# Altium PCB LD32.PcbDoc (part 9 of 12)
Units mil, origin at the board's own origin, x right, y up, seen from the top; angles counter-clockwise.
Board outline 7007.87 x 4368.85 mil, 12 copper layers (Top Layer, Int1 (GND), Int2 (AVDD), Int3 (DVDD), Int4 (GND), Int5 (ST), Int6 (SB), Int8 (AGND), Int7 (AVCC), Int9 (VCCA), Int10 (GND), Bottom Layer), stack 60.136 mil thick; 1165 components, 667 nets, 3910 pads, 2570 vias.
Unrouted connection lines stored in the file: 14.
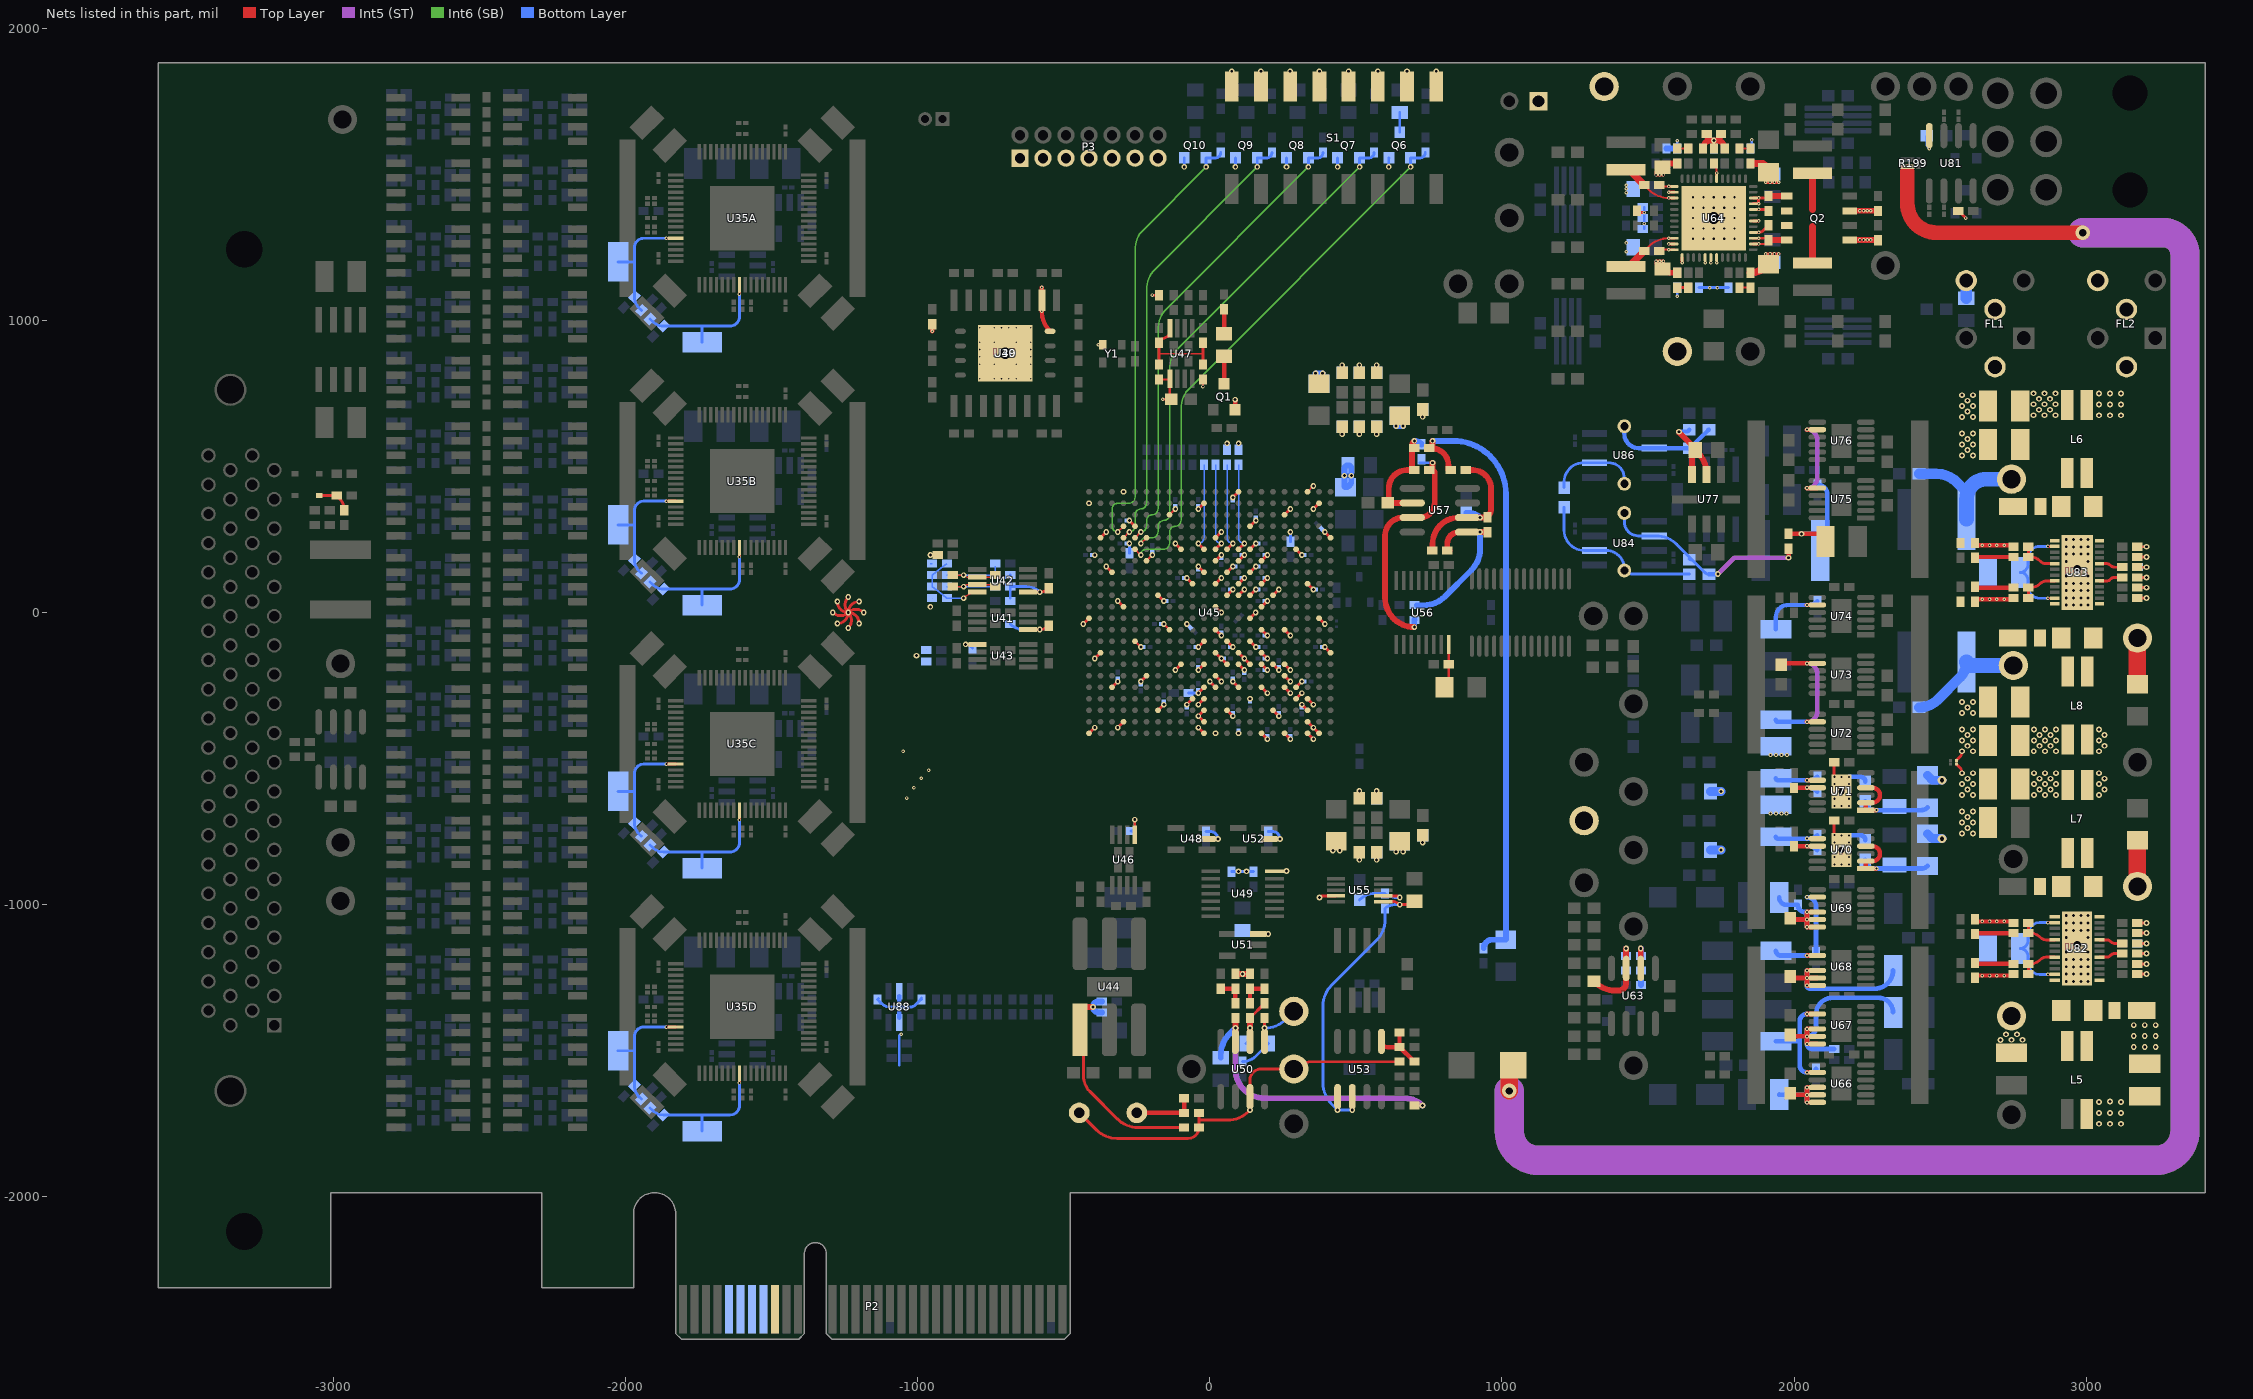
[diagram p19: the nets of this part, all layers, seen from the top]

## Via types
v1: diameter 12, hole 6, Top Layer to Bottom Layer, tented both sides, 1500 vias
v2: diameter 19, hole 10, Top Layer to Bottom Layer, tented both sides, 404 vias
v3: diameter 20, hole 10, Top Layer to Bottom Layer, tented both sides, 337 vias
v4: diameter 14, hole 7, Top Layer to Bottom Layer, tented both sides, 212 vias
v5: diameter 30, hole 15, Top Layer to Bottom Layer, tented both sides, 37 vias
v6: diameter 19.68, hole 7.87, Top Layer to Bottom Layer, 25 vias
v7: diameter 40, hole 20, Top Layer to Bottom Layer, tented both sides, 16 vias
v8: diameter 19.02, hole 10, Top Layer to Bottom Layer, tented both sides, 10 vias
v9: diameter 40, hole 20, Top Layer to Bottom Layer, 9 vias
v10: diameter 60, hole 40, Top Layer to Bottom Layer, 5 vias
v11: diameter 25, hole 13, Top Layer to Bottom Layer, 4 vias
v12: diameter 50, hole 25, Top Layer to Bottom Layer, tented both sides, 4 vias
v13: diameter 35, hole 20, Top Layer to Bottom Layer, 2 vias
v14: diameter 50, hole 25, Top Layer to Bottom Layer, 2 vias
v15: diameter 63, hole 45, Top Layer to Bottom Layer, 1 vias
v16: diameter 14.02, hole 7.01, Top Layer to Bottom Layer, tented both sides, 1 vias
v17: diameter 60, hole 40, Top Layer to Bottom Layer, tented both sides, 1 vias

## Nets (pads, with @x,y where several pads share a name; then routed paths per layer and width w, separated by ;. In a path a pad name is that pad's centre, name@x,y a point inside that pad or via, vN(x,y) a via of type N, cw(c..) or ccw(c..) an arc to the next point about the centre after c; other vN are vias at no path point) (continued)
GND: C62.1 C63.1 C65.1 C69.1 C70.1 C71.2 C72.1 C73.1 C74.1 C75.1 C76.1 C77.1 C78.1 C79.1 C80.1 C81.1 C82.1 C83.1 C84.1 C85.1 C91.1 C92.1 C100.1 C103.1 C104.1 C106.1 C107.1 C108.2 C109.1 C110.1 C111.1 C112.2 C113.1 C118.2 C119.1 C120.2 C121.1 C122.1 C123.2 C124.2 C125.1 C126.2 C127.1 C128.2 C129.2 C130.2 C131.1 C132.1 C137.1 C138.1 C139.2 C140.2 C141.1 C142.2 C143.2 C146.2 C147.2 C148.1 C149.1 C153.1 C154.1 C159.1 C160.1 C163.2 C164.2 C172.1 C173.2 C174.2 C175.2 C176.1 C182.1 C183.1 C185.1 C186.1 C189.1 C190.1 C191.1 C192.1 C194.2 C199.1 C200.1 C201.1 C202.1 C204.1 C205.1 C206.1 C207.1 C208.1 C209.1 C210.2 C211.1 C212.1 C213.2 C214.1 C216.2 C217.1 C218.2 C219.2 C220.2 C221.2 C222.2 C223.2 C224.2 C225.2 C226.2 C227.1 C228.1 C229.1 C230.1 C231.2 C232.2 C235.1 C236.2 C237.2 C238.1 C239.1 C240.1 C241.1 C242.2 C243.2 C244.1 C245.1 C246.2 C247.1 C249.1 C250.1 C251.1 C252.1 C253.1 C254.1 C255.1 C256.1 C257.1 C258.1 C259.1 C260.1 C261.1 C262.1 C263.1 C264.1 C265.1 C266.1 C268.2 C269.1 C270.1 C271.1 C273.1 C281.1 C283.1 C286.2 D7.2 FL1.4 FL1.5 FL1.6 FL2.4 FL2.5 FL2.6 FR8.1 L6.3 L7.3 L8.4 P3.1 P3.3 P3.5 P3.7 P3.9 P3.11 P3.13 P4.1 Q1.2 Q2.1 Q2.3 Q6.2 Q7.2 Q8.2 Q9.2 Q10.2 R69.2 R70.2 R98.2 R100.2 R148.2 R154.2 R156.2 R170.1 R171.1 R182.1 R183.1 R187.2 R188.2 R211.1 R212.1 R214.2 R217.2 R219.2 R220.2 R221.1 R237.1 R238.1 R246.1 R251.2 R256.2 R261.2 R265.1 R266.1 R267.1 R268.1 R269.2 R293.2 R294.2 R305.2 R306.2 R307.2 R309.1 R312.2 R314.1 R315.2 R316.1 S1.1 S1.2 S1.3 S1.4 S1.5 S1.6 S1.7 S1.8 TP13.1 TP16.1 TP23.1 TP32.1 U39.10 U40.4 U40.9 U41.5 U42.5 U43.5 U45.A2 U45.A3 U45.A5 U45.A7 U45.A9 U45.A11 U45.A12 U45.A22 U45.AA2 U45.AA12 U45.AA22 U45.AB9 U45.AB19 U45.B3 U45.B12 U45.B19 U45.C3 U45.C6 U45.C10 U45.C12 U45.C16 U45.D3 U45.D4 U45.D8 U45.D12 U45.D13 U45.E4 U45.E5 U45.E7 U45.E9 U45.E11 U45.E12 U45.E20 U45.F5 U45.F11 U45.F17 U45.G5 U45.G6 U45.G7 U45.G8 U45.G9 U45.G10 U45.G12 U45.G14 U45.H1 U45.H7 U45.H9 U45.H11 U45.H21 U45.J8 U45.J10 U45.J12 U45.J18 U45.K5 U45.K7 U45.K11 U45.K15 U45.L2 U45.L8 U45.L22 U45.M7 U45.M11 U45.M19 U45.N6 U45.N8 U45.N9 U45.N10 U45.N16 U45.P3 U45.P7 U45.P9 U45.P11 U45.P13 U45.R8 U45.R10 U45.R12 U45.R20 U45.T7 U45.T9 U45.T11 U45.T17 U45.U4 U45.U8 U45.U14 U45.V1 U45.V11 U45.V21 U45.W8 U45.W18 U45.Y5 U45.Y15 U46.5 U47.5 U48.2 U49.7 U51.3 U52.2 U55.9 U64.2 U64.11 U64.13 U64.17 U64.18 U64.19 U64.30 U64.49 U70.9 U70.13 U71.9 U71.13 U81.4 U82.25 U83.25 U88.2 U88.5 W1.1 W2.1 Y1.2 | length 8686.6
  Top Layer w7.99: U45.Y15@-137.8,334.65 v2(-118.11,354.33)
  Top Layer w8: U45.J18@-255.91,-98.43 v2(-236.22,-118.11) ; U45.T17@-216.54,177.17 v2(-196.85,196.85) ; v1(-196.85,1086.42) R100.2@-173.43,1086.42 ; R98.2@-173.43,797.74 -138.48,797.74 U47.5@-136.81,799.41 -136.81,729.58 v1(-160.93,729.58) ; v2(-157.48,-39.37) U45.K15@-137.8,-59.06 ; v1(-23.43,773.33) C69.1@-23.43,797.74
  Top Layer w10: v2(-956.69,196.85) R70.2@-931.1,196.85 ; v2(-835.96,-109.25) U43.5@-795.08,-109.25 ; U41.5@-622.24,-58.07 v2(-582.07,-58.07) ccw(c-582.07,-14.39) C63.1@-551.18,-45.28 ; U42.5@-622.24,69.88 v2(-582.07,69.88) ccw(c-582.07,113.57) C62.1@-551.18,82.68 ; v2(-433.07,-39.37) U45.L22@-413.39,-19.68 ; U45.A22@-413.39,-413.39 v2(-393.7,-393.7) ; v2(-393.72,-157.48) U45.H21@-374.02,-137.8 ; v1(-381.89,916.34) Y1.2@-367.13,916.34 ; U45.V21@-374.02,255.91 v2(-354.33,275.59) ; v2(-354.33,157.48) U45.R20@-334.65,137.8 ; U45.E20@-334.65,-255.91 U45.E20@-334.65,-255.91 v2(-314.96,-236.35) v2(-314.96,-236.35) ; v2(-314.96,-393.7) U45.B19@-295.28,-374.02 ; v2(-314.96,39.37) U45.M19@-295.28,19.69 ; v2(-275.59,314.96) U45.W18@-255.91,295.28 ; U46.5@-256.89,-760.04 v2(-256.89,-708.66) ; v2(-236.22,-236.22) U45.F17@-216.54,-216.54 ; U45.C16@-177.17,-334.65 v2(-157.48,-314.96) ; U45.N16@-177.17,59.06 v2(-157.48,39.37) ; v2(-118.11,-196.85) U45.G14@-98.43,-177.17 ; v2(-118.11,236.22) U45.U14@-98.43,216.54 ; v2(-78.74,-314.96) U45.D13@-59.05,-295.28 ; v2(-78.74,118.11) U45.P13@-59.05,98.43 ; v2(-39.37,-393.7) U45.A12@-19.68,-413.39 ; v2(-39.37,-314.96) U45.D12@-19.68,-295.28 ; v2(-39.37,-275.59) U45.E12@-19.68,-255.91 ; v2(-39.37,-196.85) U45.G12@-19.68,-177.17 ; v2(-39.37,-118.11) U45.J12@-19.68,-98.43 ; v2(-39.37,157.48) U45.R12@-19.68,137.8 ; v2(-39.37,354.33) U45.AA12@-19.68,374.02 ; U45.B12@-19.68,-374.02 v2(-39.37,-354.33) U45.C12@-19.68,-334.65 ; U48.2@-9.35,-775 v3(27.5,-775) ; v2@0,-236.22 U45.E11@19.69,-255.91 ; U45.F11@19.69,-216.54 v2(39.37,-236.22) ; U45.H11@19.69,-137.8 v2(39.37,-157.48) U45.G10@59.06,-177.17 ; U45.K11@19.69,-59.06 v2(39.37,-78.74) ; U45.M11@19.69,19.69 v2(39.37,0) ; U45.P11@19.69,98.43 v2(39.37,118.11) ; U45.T11@19.69,177.17 v2(39.37,196.85) ; U45.V11@19.69,255.91 v2(39.37,275.59) ; U45.C10@59.06,-334.65 v2(78.74,-354.33) ; U45.J10@59.06,-98.43 v2(78.74,-118.11) ; U45.N10@59.06,59.06 v2(78.74,78.74) ; U45.R10@59.06,137.8 v2(78.74,157.48) ; v2(78.74,-236.22) U45.E9@98.43,-255.91 ; v2(78.74,393.7) U45.AB9@98.43,413.39 ; U45.G9@98.43,-177.17 v2(118.11,-196.85) ; U45.H9@98.43,-137.8 v2(118.11,-157.48) U45.G8@137.8,-177.17 ; U45.N9@98.43,59.06 v2(118.11,78.74) ; U45.P9@98.43,98.43 v2(118.11,118.11) ; U45.T9@98.43,177.17 v2(118.11,196.85) ; U45.J8@137.8,-98.43 v2(157.48,-118.11) ; U45.L8@137.8,-19.68 v2(157.05,0) ; U45.N8@137.8,59.06 v2(157.48,78.74) ; U45.R8@137.8,137.8 v2(157.48,157.48) ; U45.U8@137.8,216.54 v2(157.48,236.22) ; U45.W8@137.8,295.28 v2(157.48,314.96) ; U45.A7@177.17,-413.39 v2(196.85,-433.07) ; U45.E7@177.17,-255.91 v2(196.85,-275.59) ; U45.G7@177.17,-177.17 v2(196.85,-196.85) ; U45.H7@177.17,-137.8 v2(196.85,-157.48) ; U45.K7@177.17,-59.06 v2(196.85,-78.74) ; U45.M7@177.17,19.69 v2(196.85,39.37) ; U45.P7@177.17,98.43 v2(196.85,118.11) ; U45.T7@177.17,177.17 v2(196.85,196.85) ; U45.C6@216.54,-334.65 v2(236.22,-354.33) ; U45.G6@216.54,-177.17 v2(236.22,-196.85) ; U45.N6@216.54,59.06 v2(236.22,78.74) ; U45.A5@255.91,-413.39 v2(275.59,-433.07) ; U45.E5@255.91,-255.91 v2(275.59,-275.59) ; U45.F5@255.91,-216.54 v2(275.59,-236.22) ; U45.G5@255.91,-177.17 v2(275.59,-196.85) ; U45.K5@255.91,-59.06 v2(275.59,-78.74) ; U45.Y5@255.91,334.65 v2(275.59,354.33) ; U45.D4@295.28,-295.28 v2(314.96,-275.59) ; U45.E4@295.28,-255.91 v2(314.96,-236.22) ; U45.U4@295.28,216.54 v2(314.96,196.85) ; v2(314.96,-314.96) U45.C3@334.65,-334.65 ; U45.A3@334.65,-413.39 v2(354.33,-433.07) ; U45.B3@334.65,-374.02 v2(354.33,-393.7) U45.A2@374.02,-413.39 ; U45.D3@334.65,-295.28 v2(354.33,-314.96) ; U45.P3@334.65,98.43 v2(354.33,78.74) ; v2(354.33,354.33) U45.AA2@374.02,374.02 ; U45.L2@374.02,-19.68 v2(393.7,-39.37) ; v3(375,-975) cw(c387.83,-987.83) 387.83,-969.68 U55.9@431.79,-969.68 ; v2(393.7,-118.11) U45.H1@413.39,-137.8 ; v2(393.7,275.59) U45.V1@413.39,255.91 ; C100.1@1462.5,1375.59 ccw(c1478.55,1391.64) 1478.55,1368.94 v1(1486.91,1368.94) ; C103.1@1527.5,1192.5 v1(1527.5,1202.5) v1(1540,1202.5) v1(1552.5,1202.5) C103.1@1552.5,1195 ; C104.1@1527.5,1510 v1(1527.5,1497.5) v1(1540,1497.5) v1(1552.5,1497.5) 1552.5,1522.5 C104.1@1550,1522.5 ; v1(1571,1261.42) U64.11@1590.16,1261.42 ; v1(1571,1438.58) U64.2@1590.16,1438.58 ; v1(1616.73,1197.36) U64.13@1616.73,1215.16 ; U64.30@1859.84,1340.16 v1(1878.54,1340.16) ; v1(1902.5,1227.5) v1(1917.5,1227.5) v1(1932.5,1227.5) v1(1947.5,1227.5) ; v1(1902.5,1472.5) v1(1917.5,1472.5) v1(1932.5,1472.5) v1(1947.5,1472.5) ; R182.1@2136.91,-712.5 2136.91,-762.2 v4(2137.5,-762.2) ; R183.1@2136.91,-512.5 2136.91,-562.2 v4(2137.5,-562.2) ; v1(2462.5,1587.5) U81.4@2462.5,1631.99 ; W1.1@2555,-518.75 2567.05,-530.79 cw(c2547.84,-550) v3(2575,-550) ; W2.1@2555,-506.25 2567.05,-494.2 ccw(c2547.84,-475) v3(2575,-475) ; C146.2@2561.91,1375 cw(c2561.91,1373.57) 2562.92,1374.58 v1(2587.5,1350) ; R214.2@3174.34,-1202.5 v3(3206.25,-1202.5) ; C139.2@3174.34,-1167.5 v3(3206.25,-1167.5) ; C137.1@3174.34,-1132.5 v3(3206.25,-1132.5) ; R211.1@3174.34,-1097.5 v3(3206.25,-1097.5) ; R217.2@3174.34,85 v3(3206.25,85) ; C140.2@3174.34,120 v3(3206.25,120) ; C138.1@3174.34,155 v3(3206.25,155) ; R212.1@3174.34,190 v3(3206.25,190) ; v3(-1237.5,0) cw(c-1237.5,-37.5) v3(-1200,-37.5) ccw(c-1237.5,-37.5) v3(-1237.5,0) ; v3(-1237.5,0) cw(c-1264.02,-26.52) v3(-1237.5,-53.03) ccw(c-1264.02,-26.52) v3(-1237.5,0) ; v3(-1237.5,0) cw(c-1237.5,37.5) v3(-1275,37.5) ccw(c-1237.5,37.5) v3(-1237.5,0) ; v3(-1237.5,0) cw(c-1210.98,26.52) v3(-1237.5,53.03) ccw(c-1210.98,26.52) v3(-1237.5,0) ; v3(-1237.5,0) cw(c-1264.02,26.52) v3(-1290.53,0) ccw(c-1264.02,26.52) v3(-1237.5,0) ; v3(-1237.5,0) cw(c-1200,0) v3(-1200,37.5) ccw(c-1200,0) v3(-1237.5,0) ; v3(-1237.5,0) cw(c-1210.98,-26.52) v3(-1184.47,0) ccw(c-1210.98,-26.52) v3(-1237.5,0) ; v3(-1237.5,0) cw(c-1275,0) v3(-1275,-37.5) ccw(c-1275,0) v3(-1237.5,0)
  Top Layer w15: v1(-950,962.5) R69.2@-950,986.91 ; v1(-575,1112.5) U39.10@-575,1068.6 v1(-575,1031.41) ccw(c-477.54,1031.41) U40.4@-546.46,962.5 ; C118.2@2618.75,-1250.59 cw(c2626.84,-1250.59) 2626.84,-1242.5 v1(2643.75,-1242.5) v1(2668.75,-1242.5) v1(2693.75,-1242.5) v1(2718.75,-1242.5) 2745.66,-1242.5 ccw(c2745.66,-1237.5) C129.2@2750.66,-1237.5 ; C119.1@2618.75,-1049.41 ccw(c2626.84,-1049.41) 2626.84,-1057.5 v1(2643.75,-1057.5) v1(2668.75,-1057.5) v1(2693.75,-1057.5) v1(2718.75,-1057.5) 2745.66,-1057.5 cw(c2745.66,-1062.5) C131.1@2750.66,-1062.5 ; C120.2@2618.75,36.91 cw(c2626.84,36.91) 2626.84,45 v1(2693.75,45) v1(2718.75,45) 2745.66,45 ccw(c2745.66,50) C130.2@2750.66,50 ; C121.1@2618.75,238.09 ccw(c2626.84,238.09) 2626.84,230 v1(2643.75,230) v1(2668.75,230) 2745.66,230 cw(c2745.66,225) C132.1@2750.66,225
  Top Layer w15.98: Q1.2@86.61,693.9 v2(86.61,728.35)
  Top Layer w16: R170.1@2000,-800.59 2000.89,-799.7 v4(2043.75,-799.7) U70.9@2079.44,-799.7 ; R171.1@2000,-600.59 2000.89,-599.7 v4(2043.75,-599.7) U71.9@2079.44,-599.7
  Top Layer w20: C70.1@87.5,-1236.91 C71.2@137.5,-1236.91 ; C103.1@1550,1175.89 ccw(c1580.89,1206.78) 1580.89,1163.09 C106.1@1600,1163.09 ; C104.1@1550,1524.11 cw(c1580.89,1493.22) 1580.89,1536.91 C107.1@1600,1536.91 ; C108.2@1687.5,1588.09 cw(c1714.41,1588.09) 1714.41,1615 v3@1723.09,1615 ; R148.2@1700.59,1637.5 ccw(c1723.09,1637.5) v3@1723.09,1615 ; C109.1@1725,1588.09 v3(1725,1615) ; R154.2@1749.41,1637.5 cw(c1726.91,1637.5) v3@1726.91,1615 ; R156.2@1762.5,1588.09 ccw(c1735.59,1588.09) 1735.59,1615 v3@1726.91,1615 ; Q2.1@2190.16,1275 v1(2225,1275) v1(2237.5,1275) v1(2250,1275) v1(2262.5,1275) 2286.07,1275 cw(c2286.07,1272.98) R187.2@2287.5,1274.41 ; Q2.3@2190.16,1375 v1(2225,1375) v1(2237.5,1375) v1(2250,1375) v1(2262.5,1375) 2286.07,1375 cw(c2286.07,1372.98) R188.2@2287.5,1374.41 ; v3@1723.09,1615 v3(1725,1615) ; v3(1725,1615) v3@1726.91,1615
  Top Layer w25: C110.1@1850,1163.09 ccw(c1850,1242.69) 1906.29,1186.41 C112.2@1912.5,1192.62 ; C111.1@1850,1536.91 1882.97,1536.91 cw(c1882.97,1507.38) C113.1@1912.5,1507.38 C113.1@1906.29,1513.59
  Bottom Layer w5: C283.1@-956.69,167.32 C283.1@-950.79,167.32
  Bottom Layer w7: C176.1@1486.91,1312.5 v1(1486.91,1331.21) v1(1486.91,1368.94) R268.1@1486.91,1387.5
  Bottom Layer w8: -1062.5,-1550 -1062.5,-1450 cw(c-1056.25,-1450) v1(-1056.25,-1443.75)
  Bottom Layer w10: C286.2@-1134.24,-1321.15 C286.2@-1137.5,-1324.41 -1124.28,-1337.63 ccw(c-1094.41,-1307.75) -1094.41,-1350 -1062.5,-1350 -1023.44,-1350 ccw(c-1023.44,-1328.73) -1008.4,-1343.77 R316.1@-990.12,-1325.5 ; R316.1@-987.5,-1324.41 ccw(c-987.5,-1328.12) -990.11,-1325.48 ccw(c-996.45,-1319.17) R316.1@-987.5,-1319.17 ; v2(-835.96,-109.25) cw(c-835.96,-135.72) -817.25,-117 C281.1@-812.5,-121.75 ; R305.2@-683.07,-39.37 ccw(c-637.92,5.78) -637.92,-58.07 v2(-582.07,-58.07) ; R306.2@-683.07,49.21 R307.2@-683.07,88.58 ; R309.1@-683.07,127.95 R307.2@-683.07,88.58 ; v2(-582.07,69.88) ccw(c-627.22,24.73) -627.22,88.58 R307.2@-683.07,88.58 ; C268.2@-275.59,202.76 v2(-275.59,236.22) ; C266.1@-269.69,-748.03 ccw(c-269.69,-735.24) -256.89,-735.24 v2(-256.89,-708.66) ; v2(-87.5,1525) -87.5,1555.61 Q10.2@-87.4,1555.71 ; C257.1@-72.83,-275.72 -39.37,-275.72 v2(-39.37,-275.59) ; C249.1@-12.5,-749.41 1.91,-749.41 cw(c1.91,-775) v3(27.5,-775) ; C245.1@75,-886.91 C230.1@150,-886.91 ; v2(87.5,1525) 87.5,1555.61 Q9.2@87.6,1555.71 ; C217.1@200,-749.41 214.41,-749.41 cw(c214.41,-775) v3(240,-775) ; v2(262.5,1525) 262.5,1555.61 Q8.2@262.6,1555.71 ; C212.1@275.59,242.13 v2(275.59,275.59) ; v2(437.5,1525) 437.5,1555.61 Q7.2@437.6,1555.71 ; v2(612.5,1525) 612.5,1555.61 Q6.2@612.6,1555.71 ; v1(1600,1082.5) R265.1@1600,1111.91 ; R266.1@1600,1588.09 v1(1600,1615) ; R261.2@1675,1111.91 v1(1711.57,1111.91) v1(1737.5,1111.91) R251.2@1775,1111.91 ; R246.1@1850,1588.09 ccw(c1837.93,1600.16) 1855,1600.16 v1(1855,1617.5) ; v1(1902.5,1472.5) v1(1917.5,1472.5) v1(1932.5,1472.5) v1(1947.5,1472.5) ; R221.1@2454.04,1631.25 2454.04,1607.94 ccw(c2482.94,1607.94) v1(2462.5,1587.5) ; R220.2@3174.34,-1132.5 v3(3206.25,-1132.5) ; R219.2@3175.59,155 v3(3206.25,155)
  Bottom Layer w15: U88.5@-1062.5,-1387.4 -1062.5,-1350 U88.2@-1062.5,-1312.6
  Bottom Layer w16: v4(2043.75,-799.7) 2047.12,-799.7 cw(c2047.12,-845.41) R237.1@2079.44,-813.09 ; v4(2043.75,-599.7) 2047.12,-599.7 cw(c2047.12,-645.41) R238.1@2079.44,-613.09 ; v4(2187.5,-762.5) 2227.21,-762.5 cw(c2227.21,-779.04) C153.1@2243.75,-779.04 ; v4(2187.5,-562.5) 2227.21,-562.5 cw(c2227.21,-579.04) C154.1@2243.75,-579.04
  Bottom Layer w20: v2(362.2,818.9) v2(385.83,818.9) ; v2(637.8,637.8) v2(661.42,637.8) ; R267.1@1562.5,1588.09 R266.1@1600,1588.09 ; R256.2@1725,1588.09 v3(1725,1615) ; FR8.1@460.63,433.07 ccw(c464.57,433.07) FR8.1@464.57,429.13 ccw(c464.57,448.82) 484.25,448.82 v2(484.25,468.5) 484.25,493.11 ccw(c473.43,493.11) C194.2@473.43,503.94 ccw(c473.43,491.14) 460.63,491.14 v2(460.63,468.5) FR8.1@460.63,433.07
  Bottom Layer w30: C172.1@1713.39,-812.5 v8(1750,-812.5) ; C173.2@1713.39,-612.5 v8(1750,-612.5) ; C148.1@2456.25,-757.38 2472.75,-773.88 2506.01,-773.88 v5(2506.25,-774.11) ; C149.1@2456.25,-557.38 2472.75,-573.88 2506.01,-573.88 v5(2506.25,-574.11)
  Bottom Layer w40: C147.2@2589.07,1075.89 FL1.4@2589.07,1135.93
  other v1: -1037.5,-635 -1012.5,-600 -987.5,-567.5 -962.5,-540 -1050,-475 2643.75,45 2668.75,45 2693.75,230 2718.75,230 -787.5,800 -737.75,800.06 -712.75,800.06 -687.75,800.06 -662.75,800.06 -612.75,800.06 -787.5,850 -737.75,850.06 -662.75,850.06 -612.75,850.06 -787.5,875 -612.75,875.06 -787.5,900 -612.75,900.06 -787.5,925 -737.75,925.06 -662.75,925.06 -612.75,925.06 -787.5,975 -737.75,975.06 -712.75,975.06 -687.75,975.06 -662.75,975.06 -612.75,975.06 1695.47,1197.36 1715.16,1197.36 1734.84,1197.36 1425,1235 1425,1265 1425,1437.5 1425,1450 1425,1462.5
  other v2: 511.81,-846.46 570.87,-846.46 637.8,-818.9 661.42,-818.9 421.26,-814.96 444.88,-814.96 728.35,-787.4 511.81,-610.24 570.87,-610.24 19.69,-413.39 98.43,-413.39 137.8,-295.28 0,-236.13 -1003.94,-147.64 -78.74,-39.37 -956.69,19.4 -393.72,196.49 -413.39,374.02 -295.28,413.39 59.06,578.74 98.43,578.74 452.76,610.24 511.81,610.24 570.87,610.24 728.35,669.29 452.76,846.46 511.81,846.46 570.87,846.46 75,1852.5 175,1852.5 275,1852.5 375,1852.5 475,1852.5 575,1852.5 675,1852.5 775,1852.5
  other v3: 3162.5,-1487.5 3200,-1487.5 3237.5,-1487.5 2706.25,-1463.75 2743.75,-1462.5 2781.25,-1462.5 3162.5,-1450 3200,-1450 3237.5,-1450 2725,-1443.75 2762.5,-1443.75 3162.5,-1412.5 3200,-1412.5 3237.5,-1412.5 2931.25,-1262.5 2956.25,-1262.5 2981.25,-1262.5 3006.25,-1262.5 2931.25,-1237.5 2956.49,-1237.69 2981.49,-1237.69 3006.25,-1237.5 112.5,-1236.91 2931.25,-1212.5 2956.49,-1212.69 2981.25,-1212.5 3006.25,-1212.5 2931.25,-1187.5 2956.25,-1187.5 2981.25,-1187.5 3006.25,-1187.5 2931.25,-1162.5 3006.25,-1162.5 2931.25,-1112.5 3006.25,-1112.5 200,-1100 2931.25,-1087.5 2956.49,-1087.69 2981.49,-1087.69 3006.25,-1087.5 2931.25,-1062.5 2956.49,-1062.69 2981.49,-1062.69 3006.25,-1062.5 2931.25,-1037.5 2956.25,-1037.5 2981.25,-1037.5 3006.25,-1037.5 98.43,-885.83 125.98,-885.83 262.5,-885 2575,-756.25 2612.5,-756.25 2593.75,-737.5 2575,-718.75 2612.5,-718.75 2593.75,-700 2575,-681.25 2612.5,-681.25 2575,-625 2612.5,-625 3043.75,-625 2593.75,-606.25 3062.5,-606.25 2575,-587.5 2612.5,-587.5 3043.75,-587.5 2593.75,-568.75 3062.5,-568.75 2612.5,-550 3043.75,-550 2612.5,-475 3043.75,-475 2593.75,-456.25 3062.5,-456.25 2575,-437.5 2612.5,-437.5 3043.75,-437.5 2593.75,-418.75 3062.5,-418.75 2575,-400 2612.5,-400 3043.75,-400 2575,-343.75 2612.5,-343.75 2593.75,-325 2575,-306.25 2612.5,-306.25 2931.25,25 2956.25,25 2981.25,25 3006.25,25 2956.49,49.81 2981.49,49.81 2931.25,50 3006.25,50 2956.49,74.81 2931.25,75 2981.25,75 3006.25,75 2931.25,100 2956.25,100 2981.25,100 3006.25,100 2931.25,125 3006.25,125 2931.25,175 3006.25,175 2956.49,199.81 2981.49,199.81 2931.25,200 3006.25,200 2956.49,224.81 2981.49,224.81 2931.25,225 3006.25,225 2931.25,250 2956.25,250 2981.25,250 3006.25,250 2575,537.5 2612.5,537.5 2593.75,556.25 2575,575 2612.5,575 2593.75,593.75 2575,612.5 2612.5,612.5 2575,668.75 2612.5,668.75 3043.75,675 3081.25,675 3118.75,675 2593.75,687.5 2575,706.25 2612.5,706.25 3043.75,712.5 3081.25,712.5 3118.75,712.5 2593.75,725 2575,743.75 2612.5,743.75 3043.75,750 3081.25,750 3118.75,750
  other v4: 2137.5,-862.5 2162.5,-862.5 2187.5,-862.5 2137.5,-837.5 2187.5,-837.5 2137.5,-787.5 2187.5,-787.5 2162.5,-762.5 1918.75,-687.5 1937.5,-687.5 1956.25,-687.5 1973.75,-687.5 2137.5,-662.5 2162.5,-662.5 2187.5,-662.5 2137.5,-637.5 2187.5,-637.5 2137.5,-587.5 2187.5,-587.5 2162.5,-562.5 1918.75,-487.5 1937.5,-487.5 1956.25,-487.5 1975,-487.5
  other v6: 1654.13,1279.13 1689.57,1279.13 1725,1279.13 1760.43,1279.13 1795.87,1279.13 1654.13,1314.57 1689.57,1314.57 1725,1314.57 1760.43,1314.57 1795.87,1314.57 1654.13,1350 1689.57,1350 1725,1350 1760.43,1350 1795.87,1350 1654.13,1385.43 1689.57,1385.43 1725,1385.43 1760.43,1385.43 1795.87,1385.43 1654.13,1420.87 1689.57,1420.87 1725,1420.87 1760.43,1420.87 1795.87,1420.87
  other v9: 2162.5,-812.5 2162.5,-612.5
  other v10: 1725,1350
  other v14: 2968.75,-1137.5 2968.75,150
  other v17: -700,887.5
GP1A: C311A.1 R323A.1 TP41A.1 U35A.40 | length 497.1
  Top Layer w10: v1(-1609.84,1090) U35A.40@-1609.84,1122.5
  Bottom Layer w10: R323A.1@-1915.6,1004.4 -1907.61,996.42 ccw(c-1869.4,1034.63) C311A.1@-1869.4,980.6 -1641.75,980.6 ccw(c-1641.75,1012.5) -1609.84,1012.5 v1(-1609.84,1090) ; TP41A.1@-1737.5,925 -1737.5,980.6
GP1B: C311B.1 R323B.1 TP41B.1 U35B.40 | length 497.1
  Top Layer w10: v1(-1609.84,190) U35B.40@-1609.84,222.5
  Bottom Layer w10: R323B.1@-1915.6,104.4 -1907.61,96.42 ccw(c-1869.4,134.63) C311B.1@-1869.4,80.6 -1641.75,80.6 ccw(c-1641.75,112.5) -1609.84,112.5 v1(-1609.84,190) ; TP41B.1@-1737.5,25 -1737.5,80.6
GP1C: C311C.1 R323C.1 TP41C.1 U35C.40 | length 497.1
  Top Layer w10: v1(-1609.84,-710) U35C.40@-1609.84,-677.5
  Bottom Layer w10: R323C.1@-1915.6,-795.6 -1907.61,-803.58 ccw(c-1869.4,-765.37) C311C.1@-1869.4,-819.4 -1641.75,-819.4 ccw(c-1641.75,-787.5) -1609.84,-787.5 v1(-1609.84,-710) ; TP41C.1@-1737.5,-875 -1737.5,-819.4
GP1D: C311D.1 R323D.1 TP41D.1 U35D.40 | length 497.4
  Top Layer w10: v1(-1609.84,-1610) U35D.40@-1609.84,-1577.5
  Bottom Layer w8: -1737.5,-1720.04 -1736.87,-1719.4
  Bottom Layer w10: R323D.1@-1915.6,-1695.6 -1907.61,-1703.58 ccw(c-1869.4,-1665.37) C311D.1@-1869.4,-1719.4 -1641.75,-1719.4 ccw(c-1641.75,-1687.5) -1609.84,-1687.5 v1(-1609.84,-1610) ; TP41D.1@-1737.5,-1775 -1737.5,-1720.04
GP2A: C315A.1 R331A.1 TP45A.1 U35A.28 | length 438.8
  Top Layer w10: v1(-1860,1281.1) U35A.28@-1827.5,1281.1
  Bottom Layer w10: TP45A.1@-2025,1200 -1971.2,1200 -1969.4,1201.79 ; R331A.1@-1945.6,1034.4 -1953.58,1042.39 cw(c-1915.37,1080.6) C315A.1@-1969.4,1080.6 -1969.4,1249.2 cw(c-1937.5,1249.2) -1937.5,1281.1 v1(-1860,1281.1)
GP2B: C315B.1 R331B.1 TP45B.1 U35B.28 | length 438
  Top Layer w10: v1(-1860,381.1) U35B.28@-1827.5,381.1
  Bottom Layer w10: TP45B.1@-2025,300 -1969.4,300 ; R331B.1@-1945.6,134.4 -1953.58,142.39 cw(c-1915.37,180.6) C315B.1@-1969.4,180.6 -1969.4,349.2 cw(c-1937.5,349.2) -1937.5,381.1 v1(-1860,381.1)
GP2C: C315C.1 R331C.1 TP45C.1 U35C.28 | length 438.3
  Top Layer w10: v1(-1860,-518.9) U35C.28@-1827.5,-518.9
  Bottom Layer w10: TP45C.1@-2025,-612.5 -1970,-612.5 -1969.4,-613.09 ; R331C.1@-1945.6,-765.6 -1953.58,-757.61 cw(c-1915.37,-719.4) C315C.1@-1969.4,-719.4 -1969.4,-550.8 cw(c-1937.5,-550.8) -1937.5,-518.9 v1(-1860,-518.9)
GP2D: C315D.1 R331D.1 TP45D.1 U35D.28 | length 438.3
  Top Layer w10: v1(-1860,-1418.9) U35D.28@-1827.5,-1418.9
  Bottom Layer w5: -1970.14,-1500 -1969.4,-1500.73
  Bottom Layer w10: TP45D.1@-2025,-1500 -1970.14,-1500 ; R331D.1@-1945.6,-1665.6 -1953.58,-1657.61 cw(c-1915.37,-1619.4) C315D.1@-1969.4,-1619.4 -1969.4,-1450.8 cw(c-1937.5,-1450.8) -1937.5,-1418.9 v1(-1860,-1418.9)
INIT: R298.1 U45.U12 | length 308.8
  Top Layer w10: v2(-39.37,236.22) U45.U12@-19.68,216.54
  Bottom Layer w5: v2(-39.37,236.22) ccw(c-39.37,255.91) -19.68,255.91 R298.1@-19.69,505.91
JTAG1: P2.B9
JTAG2: P2.A5
JTAG3: P2.A6
JTAG4: P2.A7
JTAG5: P2.A8
LED_A: Q9.1 R290.1 U45.V19 | length 1555.2
  Top Layer w5: U45.V19@-295.28,255.91 v2(-275.59,275.59)
  Int6 (SB) w5: v2(-275.59,275.59) ccw(c-275.59,295.28) -255.91,295.28 -255.91,334.65 cw(c-236.22,334.65) -236.22,354.33 ccw(c-236.22,374.02) -216.54,374.02 -216.54,1104.54 cw(c-116.54,1104.54) -187.25,1175.25 v2(162.5,1525)
  Bottom Layer w10: v2(162.5,1525) 162.5,1555.61 Q9.1@162.4,1555.71 193.8,1555.71 ccw(c193.8,1574.41) R290.1@212.5,1574.41
LED_B: Q8.1 R288.1 U45.V18 | length 1611.4
  Top Layer w5: U45.V18@-255.91,255.91 v2(-236.22,275.59)
  Int6 (SB) w5: v2(-236.22,275.59) ccw(c-236.22,295.28) -216.54,295.28 -216.54,314.96 cw(c-196.85,314.96) -196.85,334.65 ccw(c-196.85,354.33) -177.17,354.33 -177.17,968.91 cw(c-77.17,968.91) -147.88,1039.62 v2(337.5,1525)
  Bottom Layer w10: v2(337.5,1525) 337.5,1555.61 Q8.1@337.4,1555.71 368.8,1555.71 ccw(c368.8,1574.41) R288.1@387.5,1574.41
LED_C: Q7.1 R285.1 U45.V17 | length 1738
  Top Layer w5: v2(-236.22,236.22) U45.V17@-216.54,255.91
  Int6 (SB) w5: v2(-236.22,236.22) cw(c-216.54,236.22) -216.54,255.91 -196.85,255.91 ccw(c-196.85,275.59) -177.17,275.59 -177.17,295.28 cw(c-157.48,295.28) -157.48,314.96 -157.19,314.96 ccw(c-157.19,334.65) -137.5,334.65 -137.5,833.58 cw(c-37.5,833.58) -108.21,904.29 v2(512.5,1525)
  Bottom Layer w10: v2(512.5,1525) 512.5,1555.61 Q7.1@512.4,1555.71 543.8,1555.71 ccw(c543.8,1574.41) R285.1@562.5,1574.41
LED_D: Q6.1 R280.1 U45.U18 | length 1876.3
  Top Layer w5: U45.U18@-255.91,216.54 -239,199.63 cw(c-245.73,192.91) v2@-236.22,192.91
  Int6 (SB) w5: v2(-236.22,196.85) cw(c-216.54,196.85) -216.54,216.54 -157.48,216.54 ccw(c-157.48,236.22) -137.8,236.22 -137.8,275.59 cw(c-118.11,275.59) -118.11,295.28 ccw(c-118.11,314.96) -98.43,314.96 -98.43,697.65 cw(c1.57,697.65) -69.14,768.36 v2(687.5,1525)
  Bottom Layer w10: v2(687.5,1525) 687.5,1555.61 Q6.1@687.4,1555.71 718.8,1555.71 ccw(c718.8,1574.41) R280.1@737.5,1574.41
LED_PG: Q10.1 R295.1 U45.W19 | length 1538.4
  Top Layer w5: v2(-314.96,275.59) U45.W19@-295.28,295.28
  Int6 (SB) w5: v2(-314.96,275.59) cw(c-314.96,295.28) -334.65,295.28 -334.65,354.33 cw(c-314.96,354.33) -314.96,374.02 -275.59,374.02 ccw(c-275.59,393.7) -255.91,393.7 -255.91,1240.17 cw(c-155.91,1240.17) -226.62,1310.88 v2(-12.5,1525)
  Bottom Layer w10: v2(-12.5,1525) -12.5,1555.61 Q10.1@-12.6,1555.71 18.8,1555.71 ccw(c18.8,1574.41) R295.1@37.5,1574.41
LEDIN: U45.AB3 | length 27.8
  Top Layer w5: U45.AB3@334.65,413.39 v2(354.33,433.07)
M0: R297.1 U45.U11 | length 308.8
  Top Layer w10: U45.U11@19.69,216.54 v2(39.37,236.22)
  Bottom Layer w5: R297.1@19.69,505.91 19.69,255.91 ccw(c39.37,255.91) v2(39.37,236.22)
M1: R294.1 U45.U10 | length 308.8
  Top Layer w10: U45.U10@59.06,216.54 v2(78.74,236.22)
  Bottom Layer w5: R294.1@59.06,505.91 59.06,255.91 ccw(c78.74,255.91) v2(78.74,236.22)
M2: R293.1 U45.U9 | length 308.8
  Top Layer w10: U45.U9@98.43,216.54 v2(118.11,236.22)
  Bottom Layer w5: R293.1@98.43,505.91 98.43,255.91 ccw(c118.11,255.91) v2(118.11,236.22)
MON: C88.2 R116.2 R117.1 U53.5 | length 194.8
  Top Layer w15: U53.5@587.5,-1468.01 ccw(c606.99,-1468.01) 606.99,-1487.5 R117.1@649.41,-1487.5 ; C88.2@649.41,-1437.5 R117.1@649.41,-1487.5 ; R117.1@650.42,-1487.92 ccw(c649.41,-1488.93) R117.1@649.41,-1487.5 ; R117.1@650.42,-1487.92 699.58,-1537.08 ccw(c700.59,-1536.07) R116.2@700.59,-1537.5
NetC59_2: C59.2 R80.1 R307.1 R311.2 U42.3 | length 314.7
  Top Layer w5: C59.2@-879.92,88.58 v2(-842.52,88.58) cw(c-825.89,71.95) -825.89,95.47 U42.3@-795.47,95.47 -750.89,95.47 cw(c-750.89,71.95) R80.1@-734.25,88.58
  Bottom Layer w5: R311.2@-899.61,88.58 v2(-842.52,88.58) R307.1@-734.25,88.58
NetC60_2: C60.2 R81.1 R309.2 R310.2 R313.1 U42.2 | length 354.1
  Top Layer w5: C60.2@-879.92,127.95 v2(-842.52,127.95) ccw(c-825.89,144.59) -825.89,121.06 U42.2@-795.47,121.06 -750.89,121.06 ccw(c-750.89,144.59) R81.1@-734.25,127.95
  Bottom Layer w5: R313.1@-899.61,127.95 -884.39,127.95 v2(-842.52,127.95) R309.2@-734.25,127.95 ; R309.2@-734.25,118.11 R310.2@-734.25,157.48
NetC61_1: C61.1 C67.2 R102.2 | length 211.9
  Top Layer w15: C61.1@-250,-1712.5 C67.2@-88.09,-1712.5 R102.2@-88.09,-1662.5
NetC61_2: C61.2 C67.1 R103.2 R116.1 TP6.1 U50.7 | length 1340.4
  Top Layer w10: C61.2@-446.85,-1712.5 -388.64,-1770.71 ccw(c-317.93,-1700) -317.93,-1800 -74.41,-1800 ccw(c-74.41,-1762.5) R103.2@-36.91,-1762.5 -36.91,-1737.5 ; C67.1@-36.91,-1712.5 -36.91,-1737.5 ; R116.1@649.41,-1537.5 347.86,-1537.5 ccw(c347.86,-1622.86) TP6.1@287.5,-1562.5 175,-1562.5 ccw(c175,-1600) 137.5,-1600 U50.7@137.5,-1656.99 v3(137.5,-1702.5) 131.79,-1708.21 cw(c61.08,-1637.5) 61.08,-1737.5 -36.91,-1737.5
NetC69_2: C69.2 R98.1 R99.1 R105.2 U47.4 | length 366.6
  Top Layer w6: -173.43,885.83 -23.43,885.83
  Top Layer w10: R98.1@-173.43,848.92 -173.43,885.83 R99.1@-173.43,922.74 -164.65,935.45 -140.08,946.14 U47.4@-136.81,972.64 ; C69.2@-23.43,848.92 -23.43,885.83 R105.2@-23.43,922.74
NetC70_2: C70.2 R108.2 R110.1 | length 98.8
  Top Layer w15: R108.2@37.5,-1288.09 C70.2@87.5,-1288.09 R110.1@87.5,-1336.91
NetC71_1: C71.1 R111.1 R113.2 | length 98.8
  Top Layer w15: R111.1@137.5,-1336.91 C71.1@137.5,-1288.09 R113.2@187.5,-1288.09
NetC90_1: C90.1 R284.2 U53.1 U53.2 U55.1 | length 1001.5
  Top Layer w10: U55.1@593.21,-989.37 624.34,-989.37 cw(c624.34,-1025.66) v3(650,-1000) 671.96,-1000 ccw(c671.96,-960.35) C90.1@700,-988.39
  Bottom Layer w10: v3(487.5,-1702.5) v3(437.5,-1702.5) 416.79,-1681.79 cw(c487.5,-1611.08) 387.5,-1611.08 387.5,-1346.42 cw(c487.5,-1346.42) 416.79,-1275.71 570.71,-1121.79 ccw(c500,-1051.08) 600,-1051.08 R284.2@600,-1013.09 cw(c631.6,-1044.69) 631.6,-1000 v3(650,-1000)
NetC94_2: C94.2 FR1.1 U56.16 | length 150.6
  Top Layer w10: FR1.1@803.15,-255.91 ccw(c767.51,-220.26) 817.91,-220.26 C94.2@817.91,-177.17 U56.16@817.91,-109.25
NetC96_1: C96.1 R120.2 R283.1 U57.1 | length 557.8
  Top Layer w20: R120.2@820.96,212.5 cw(c820.96,220.96) 812.5,220.96 812.5,234.83 cw(c852.67,234.83) 852.67,275 U57.1@881.99,275 948.57,275 cw(c948.57,272.98) C96.1@950,274.41
  Bottom Layer w20: R283.1@708.46,25 733.58,25 ccw(c733.58,125) 804.29,54.29 895.71,145.71 ccw(c825,216.42) 925,216.42 v2@925,275
  other v2: 925,275.59
NetC96_2: C96.2 R120.1 R121.2 R279.2 U57.2 | length 535.7
  Top Layer w20: R120.1@754.04,212.5 ccw(c754.04,220.96) 762.5,220.96 762.5,234.83 cw(c852.67,234.83) 852.67,325 U57.2@881.99,325 v2(925,325) 948.57,325 ccw(c948.57,327.02) C96.2@950,325.59 ccw(c919.82,355.77) 962.5,355.77 962.5,425 ccw(c900,425) 900,487.5 R121.2@883.46,487.5
  Bottom Layer w20: R279.2@877.5,341.54 885.08,341.54 cw(c885.08,285.08) v2(925,325)
NetC98_1: C98.1 R245.1 R262.1 U86.2 | length 369
  Bottom Layer w15: C98.1@1418.75,637.5 1418.75,612.76 ccw(c1469.01,612.76) 1469.01,562.5 R262.1@1641.54,562.5 1643.5,562.5 1674.75,593.75 1675.25,593.75 1706.5,625 R245.1@1708.46,625
NetC98_2: C98.2 R270.2 U86.6 | length 312.5
  Bottom Layer w10: R270.2@1212.5,427.21 1212.5,446.49 cw(c1278.51,446.49) 1278.51,512.5 1366.11,512.5 cw(c1366.11,459.86) 1418.75,459.86 C98.2@1418.75,440.65
NetC99_1: C99.1 R231.2 R270.1 U84.2 | length 592.6
  Bottom Layer w10: R270.1@1212.5,360.29 1212.5,281.25 ccw(c1281.25,281.25) 1281.25,212.5 U84.2@1316.39,212.5 1356.25,212.5 cw(c1356.25,150) 1418.75,150 C99.1@1418.75,143.75 ccw(c1448.93,173.93) 1448.93,131.25 R231.2@1641.54,131.25
NetC99_2: C99.2 R231.1 R243.2 R500.2 U84.6 | length 756
  Top Layer w15: v3(1981.25,187.5) R500.2@1981.25,218.16
  Int5 (ST) w15: v3(1738.75,131.25) 1795,187.5 v3(1981.25,187.5)
  Bottom Layer w10: C99.2@1418.75,340.6 1418.75,310.07 ccw(c1466.32,310.07) 1466.32,262.5 1527.33,262.5 cw(c1527.33,162.5) 1598.04,233.21 1654.92,176.33 ccw(c1640,161.38) R243.2@1640,182.5 ; R243.2@1641.54,181.25 cw(c1641.54,160.81) R243.2@1655.97,175.28 ; R243.2@1654.94,176.31 R243.2@1655.97,175.28 ; R231.1@1708.46,131.25 cw(c1708.46,151.69) 1694.01,137.24 R243.2@1655.97,175.28
  Bottom Layer w15: R231.1@1708.46,131.25 v3(1738.75,131.25)
NetC101_1: C101.1 L1.1 U64.10 | length 200.2
  Top Layer w7: C101.1@1486.91,1237.5 1501.88,1252.47 cw(c1571,1183.36) v1(1571,1281.1)
  Top Layer w10: v1(1571,1281.1) U64.10@1590.16,1281.1
  Top Layer w25: L1.1@1425,1184.15 ccw(c1425,1204.83) 1439.62,1190.21 C101.1@1486.91,1237.5
NetC101_2: C101.2 U64.12 | length 53.2
  Top Layer w7: C101.2@1538.09,1237.5 cw(c1548.31,1227.28) 1548.31,1241.73 v1(1571,1241.73)
  Top Layer w10: v1(1571,1241.73) U64.12@1590.16,1241.73
NetC102_1: C102.1 L2.1 U64.3 | length 200.2
  Top Layer w7: C102.1@1486.91,1462.5 1501.88,1447.53 ccw(c1571,1516.64) v1(1571,1418.9)
  Top Layer w10: v1(1571,1418.9) U64.3@1590.16,1418.9
  Top Layer w25: L2.1@1425,1515.85 cw(c1425,1495.17) 1439.62,1509.79 C102.1@1486.91,1462.5
NetC102_2: C102.2 U64.1 | length 53.2
  Top Layer w7: C102.2@1538.09,1462.5 ccw(c1548.31,1472.72) 1548.31,1458.27 v1(1571,1458.27)
  Top Layer w10: v1(1571,1458.27) U64.1@1590.16,1458.27
NetC106_2: C106.2 R145.1 | length 37.5
  Top Layer w10: C106.2@1600,1111.91 R145.1@1637.5,1111.91
NetC107_2: C107.2 R146.1 | length 37.5
  Top Layer w7: C107.2@1600,1588.09 R146.1@1637.5,1588.09
NetC109_2: C109.2 U64.42 | length 54.7
  Top Layer w7: C109.2@1725,1536.91 cw(c1701.24,1513.15) 1734.84,1513.15 v1(1734.84,1504.04)
  Top Layer w10: U64.42@1734.84,1484.84 v1(1734.84,1504.04)
NetC110_2: C110.2 R158.1 | length 37.5
  Top Layer w7: R158.1@1812.5,1111.91 C110.2@1850,1111.91
NetC111_2: C111.2 R159.1 | length 37.5
  Top Layer w7: R159.1@1812.5,1588.09 C111.2@1850,1588.09
NetC114_1: C114.1 U64.28 | length 62
  Top Layer w10: U64.28@1859.84,1300.79 v1(1878.54,1300.79) ccw(c1878.54,1322.9) 1894.17,1307.27 C114.1@1912.5,1325.59
NetC114_2: C114.2 L3.1 Q2.7 Q2.8 U64.26 U64.27 | length 303.4
  Top Layer w8: v1(1878.54,1261.42) 1899.51,1261.42 ccw(c1899.51,1274.41) C114.2@1912.5,1274.41 ; v1(1878.54,1281.1) 1905.81,1281.1 cw(c1905.81,1274.41) C114.2@1912.5,1274.41 ; C114.2@1913.93,1275 ccw(c1913.93,1272.98) C114.2@1912.5,1274.41
  Top Layer w10: U64.26@1859.84,1261.42 v1(1878.54,1261.42) ; U64.27@1859.84,1281.1 v1(1878.54,1281.1)
  Top Layer w20: C114.2@1913.93,1275 Q2.8@1975,1275
  Top Layer w25: L3.1@2062.5,1196.65 2062.5,1320.81
NetC115_1: C115.1 U64.32 | length 54
  Top Layer w10: U64.32@1859.84,1379.53 v1(1878.54,1379.53) 1900.14,1379.53 cw(c1900.14,1362.05) C115.1@1912.5,1374.41
NetC115_2: C115.2 L4.1 Q2.5 Q2.6 U64.33 U64.34 | length 278.9
  Top Layer w10: U64.33@1859.84,1399.21 v1(1878.54,1399.21) v1(1878.54,1418.9) ; U64.34@1859.84,1418.9 v1(1878.54,1418.9) ; C115.2@1912.5,1425.59 cw(c1896.34,1441.75) 1896.34,1418.9 v1(1878.54,1418.9)
  Top Layer w20: C115.2@1912.5,1425.59 ccw(c1913.93,1427.02) 1913.93,1425 Q2.5@1975,1425
  Top Layer w25: 2062.5,1379.96 L4.1@2062.5,1503.35
NetC116_1: C116.1 R245.2 U77.6 U77.7 | length 329.9
  Top Layer w20: v3(1606.25,618.75) 1606.25,616.54 1649.3,573.48 1650,573.48 1650,528.21 ; U77.7@1650,472.15 1650,528.21 ; U77.6@1700,472.15 1700,476.44 ccw(c1600,476.44) 1670.71,547.15 C116.1@1661.61,556.25 ccw(c1689.65,528.21) 1650,528.21
  Bottom Layer w15: v3(1606.25,618.75) 1607.21,619.71 1636.24,619.71 R245.2@1641.54,625
NetC118_1: C118.1 R205.2 | length 133.7
  Top Layer w15: C118.1@2618.75,-1199.41 ccw(c2621.84,-1199.41) 2621.84,-1202.5 R205.2@2750.66,-1202.5
NetC119_2: C119.2 R209.1 | length 133.7
  Top Layer w15: C119.2@2618.75,-1100.59 cw(c2621.84,-1100.59) 2621.84,-1097.5 R209.1@2750.66,-1097.5
NetC120_1: C120.1 R206.2 | length 133.7
  Top Layer w15: C120.1@2618.75,88.09 ccw(c2621.84,88.09) 2621.84,85 R206.2@2750.66,85
NetC121_2: C121.2 R210.1 | length 133.7
  Top Layer w15: C121.2@2618.75,186.91 cw(c2621.84,186.91) 2621.84,190 R210.1@2750.66,190
NetC123_1: C123.1 C141.2 C142.1 FR4.2 L5.4 L7.4 R213.2 R215.2 TP36.1 U82.2 U82.11 | length 578.5
  Top Layer w10: v1(2868.75,-1238.58) U82.11@2892.25,-1238.58 ; v1(2868.75,-1061.42) U82.2@2892.25,-1061.42 ; R213.2@3174.34,-1237.5 v3(3206.25,-1237.5) ; R215.2@3174.34,-1062.5 v3(3206.25,-1062.5)
  Top Layer w60: TP36.1@3175,-937.5 FR4.2@3175,-780.12
  Bottom Layer w10: v1(2868.75,-1238.58) 2839.83,-1238.58 cw(c2839.83,-1198.75) 2800,-1198.75 2800,-1176.13 ccw(c2773.87,-1176.13) C142.1@2773.87,-1150 ccw(c2773.87,-1123.87) 2800,-1123.87 2800,-1101.25 cw(c2839.83,-1101.25) 2839.83,-1061.42 v1(2868.75,-1061.42)
  other v3: 3043.75,-1750 3081.25,-1750 3118.75,-1750 3043.75,-1712.5 3081.25,-1712.5 3118.75,-1712.5 3043.75,-1675 3118.75,-1675 3081.25,-1673.75 2821.25,-625 2858.75,-625 2896.25,-625 2840,-606.25 2877.5,-606.25 2821.25,-587.5 2858.75,-587.5 2896.25,-587.5 2840,-568.75 2877.5,-568.75 2821.25,-550 2858.75,-550 2896.25,-550
NetC124_1: C124.1 C127.2 C143.1 FR5.2 L6.4 L8.3 R216.2 R218.2 TP38.1 U83.2 U83.11 | length 578.5
  Top Layer w10: v1(2868.75,48.92) U83.11@2892.25,48.92 ; v1(2868.75,226.08) U83.2@2892.25,226.08 ; R216.2@3174.34,50 v3(3206.25,50) ; R218.2@3174.34,225 v3(3206.25,225)
  Top Layer w60: FR5.2@3175,-244.88 TP38.1@3175,-87.5
  Bottom Layer w10: v1(2868.75,48.92) 2839.83,48.92 cw(c2839.83,88.75) 2800,88.75 2800,111.37 ccw(c2773.87,111.37) C143.1@2773.87,137.5 ccw(c2773.87,163.63) 2800,163.63 2800,186.25 cw(c2839.83,186.25) 2839.83,226.08 v1(2868.75,226.08)
  other v3: 2820,-475 2858.75,-475 2896.25,-475 2840,-456.25 2877.5,-456.25 2821.25,-437.5 2858.75,-437.5 2896.25,-437.5 2840,-418.75 2877.5,-418.75 2821.25,-400 2858.75,-400 2896.25,-400 2819.16,675.23 2856.66,675.23 2894.16,675.23 2837.91,693.98 2875.41,693.98 2819.16,712.73 2856.66,712.73 2894.16,712.73 2837.91,731.48 2875.41,731.48 2819.16,750.23 2856.66,750.23 2894.16,750.23
NetC125_2: C125.2 C144.2 D5.2 R203.1 R227.2 TP35.1 | length 405.7
  Bottom Layer w35: R227.2@2427.21,-325 ccw(c2427.21,-234.47) 2491.23,-298.48 2567.87,-221.85 ccw(c2514.77,-168.75) C144.2@2589.86,-168.75
  Bottom Layer w50: C144.2@2589.86,-168.75 ccw(c2602.36,-168.75) 2602.36,-181.25 TP35.1@2750,-181.25
NetC126_1: C126.1 C145.1 D6.2 R204.2 R228.2 TP33.1 | length 471.1
  Bottom Layer w35: R228.2@2427.21,475 2485.94,475 cw(c2485.94,375) 2556.65,445.71 2589.86,412.5 C145.1@2589.86,387.5
  Bottom Layer w50: C145.1@2589.86,318.75 2589.86,387.5 cw(c2658.61,387.5) 2658.61,456.25 TP33.1@2743.75,456.25
NetC129_1: C129.1 R205.1 U82.8 | length 131.6
  Top Layer w10: C129.1@2801.84,-1237.5 R205.1@2801.84,-1202.5 2807.54,-1202.5 ccw(c2807.54,-1151.29) 2843.75,-1187.5 cw(c2863,-1206.75) 2863,-1179.53 U82.8@2892.25,-1179.53
NetC130_1: C130.1 R206.1 U83.8 | length 131.6
  Top Layer w10: C130.1@2801.84,50 R206.1@2801.84,85 2807.54,85 ccw(c2807.54,136.21) 2843.75,100 cw(c2863,80.75) 2863,107.97 U83.8@2892.25,107.97
NetC131_2: C131.2 R209.2 U82.5 | length 131.6
  Top Layer w10: C131.2@2801.84,-1062.5 R209.2@2801.84,-1097.5 2807.54,-1097.5 cw(c2807.54,-1148.71) 2843.75,-1112.5 ccw(c2863,-1093.25) 2863,-1120.47 U82.5@2892.25,-1120.47
NetC132_2: C132.2 R210.2 U83.5 | length 131.6
  Top Layer w10: C132.2@2801.84,225 R210.2@2801.84,190 2807.54,190 cw(c2807.54,138.79) 2843.75,175 ccw(c2863,194.25) 2863,167.03 U83.5@2892.25,167.03
NetC133_1: C133.1 D7.1 L5.1
NetC133_2: C133.2 L5.2 U82.12 U82.13
NetC134_1: C134.1 D4.1 L7.1
NetC134_2: C134.2 L7.2 U82.1 U82.24
NetC135_1: C135.1 D5.1 L8.2
NetC135_2: C135.2 L8.1 U83.12 U83.13
NetC136_1: C136.1 D6.1 L6.1
NetC136_2: C136.2 L6.2 U83.1 U83.24
NetC137_2: C137.2 U82.20 | length 81.1
  Top Layer w10: U82.20@3045.25,-1120.47 3070.32,-1120.47 cw(c3070.32,-1135.93) 3081.25,-1125 ccw(c3099.36,-1106.89) 3099.36,-1132.5 C137.2@3123.16,-1132.5
NetC138_2: C138.2 U83.20 | length 81.1
  Top Layer w10: U83.20@3045.25,167.03 3070.32,167.03 cw(c3070.32,151.57) 3081.25,162.5 ccw(c3099.36,180.61) 3099.36,155 C138.2@3123.16,155
NetC139_1: C139.1 U82.17 | length 81.5
  Top Layer w10: U82.17@3045.25,-1179.53 3070.32,-1179.53 ccw(c3070.32,-1164.07) 3081.25,-1175 3083.47,-1172.78 cw(c3096.21,-1185.51) 3096.21,-1167.5 C139.1@3123.16,-1167.5
NetC140_1: C140.1 U83.17 | length 81.5
  Top Layer w10: U83.17@3045.25,107.97 3070.32,107.97 ccw(c3070.32,123.43) 3081.25,112.5 3083.47,114.72 cw(c3096.21,101.99) 3096.21,120 C140.1@3123.16,120
NetC148_2: C148.2 C153.2 L9.2 U70.1 U70.2 U70.4 | length 419.1
  Top Layer w15: U70.4@2245.56,-799.7 2268.16,-799.7 cw(c2268.16,-825.3) 2293.75,-825.3 cw(c2268.16,-825.3) 2268.16,-850.89 U70.2@2245.56,-850.89 U70.1@2245.56,-876.48 v4(2281.25,-876.48)
  Bottom Layer w16: C153.2@2243.75,-845.96 ccw(c2274.26,-845.96) 2274.26,-876.48 v4(2281.25,-876.48) 2434.86,-876.48 ccw(c2434.86,-846.23) C148.2@2456.25,-867.62
NetC149_2: C149.2 C154.2 L10.2 U71.1 U71.2 U71.4 | length 419.1
  Top Layer w15: U71.4@2245.56,-599.7 2268.45,-599.7 cw(c2268.45,-625) 2293.75,-625 cw(c2267.86,-625) 2267.86,-650.89 U71.2@2245.56,-650.89 U71.1@2245.56,-676.48 v4(2281.25,-676.48)
  Bottom Layer w16: C154.2@2243.75,-645.96 ccw(c2274.26,-645.96) 2274.26,-676.48 v4(2281.25,-676.48) 2434.86,-676.48 ccw(c2434.86,-646.23) C149.2@2456.25,-667.62
NetC156_2: C156.2 R239.2 U74.8 | length 246.1
  Top Layer w15: v4(2043.75,25.89) U74.8@2079.44,25.89
  Bottom Layer w15: C156.2@1937.52,-57.14 1937.52,-15.48 cw(c1978.88,-15.48) 1978.88,25.89 v4(2043.75,25.89) 2049.97,25.89 ccw(c2049.97,67.56) R239.2@2079.44,38.09
NetC157_1: C157.1 R241.1 U66.8 U67.8 | length 419.4
  Top Layer w16: v4(2043.75,-1574.11) U66.8@2079.44,-1574.11 ; v4(2043.75,-1374.11) U67.8@2079.44,-1374.11
  Bottom Layer w16: C157.1@1937.5,-1467.62 2018.75,-1467.62 ; v4(2043.75,-1374.11) ccw(c2043.75,-1399.11) 2018.75,-1399.11 2018.75,-1467.62 ; R241.1@2075,-1561.91 cw(c2062.8,-1561.91) 2062.8,-1574.11 v4(2043.75,-1574.11) cw(c2043.75,-1549.11) 2018.75,-1549.11 2018.75,-1467.62
NetC158_2: C158.2 R242.2 U68.8 U69.8 | length 395.3
  Top Layer w16: v4(2043.75,-1174.11) U68.8@2079.44,-1174.11
  Bottom Layer w16: C158.2@1937.5,-1157.38 ccw(c1954.23,-1157.38) 1954.23,-1174.11 v4(2043.75,-1174.11) 2062.8,-1174.11 ccw(c2062.8,-1161.91) R242.2@2075,-1161.91 2075,-1005.36 ccw(c2043.75,-1005.36) v4(2043.75,-974.11)
NetC159_2: C159.2 R237.2 U70.8 | length 148.9
  Bottom Layer w15: C159.2@1937.5,-767.62 ccw(c1944,-767.62) 1944,-774.11 v4(2043.75,-774.11) 2049.97,-774.11 ccw(c2049.97,-732.44) R237.2@2079.44,-761.91
NetC160_2: C160.2 R238.2 U71.8 | length 184.6
  Top Layer w15: v4(2043.75,-574.11) U71.8@2079.44,-574.11
  Bottom Layer w15: C160.2@1937.5,-567.62 ccw(c1944,-567.62) 1944,-574.11 v4(2043.75,-574.11) 2049.97,-574.11 ccw(c2049.97,-532.44) R238.2@2079.44,-561.91
NetC161_2: C161.2 R160.1 U72.8 U73.8 | length 511.6
  Top Layer w15: R160.1@1956.25,-179.04 1961.17,-174.11 U73.8@2079.44,-174.11 ; v4(2043.75,-374.11) U72.8@2079.44,-374.11
  Int5 (ST) w15: v4(2043.75,-374.11) ccw(c2043.75,-338.43) 2079.44,-338.43 2079.44,-209.8 ccw(c2043.75,-209.8) v4(2043.75,-174.11)
  Bottom Layer w15: C161.2@1937.5,-367.62 ccw(c1944,-367.62) 1944,-374.11 v4(2043.75,-374.11)
NetC162_2: C162.2 C500.2 R240.2 R500.1 U75.8 U76.8 | length 893.5
  Top Layer w15: R500.1@1981.25,269.34 v3(2025,269.34) 2107.38,269.34 C162.2@2107.38,243.75 ; v4(2043.75,425.89) U75.8@2079.44,425.89 ; v4(2043.75,625.89) U76.8@2079.44,625.89
  Int5 (ST) w15: v4(2043.75,425.89) ccw(c2043.75,461.57) 2079.44,461.57 2079.44,590.2 ccw(c2043.75,590.2) v4(2043.75,625.89)
  Bottom Layer w15: v3(2025,269.34) 2089.86,269.34 C500.2@2089.86,212.5 2113.75,212.5 2113.75,403.78 ccw(c2079.44,403.78) R240.2@2079.44,438.09 cw(c2049.97,467.56) 2049.97,425.89 v4(2043.75,425.89)
NetC177_1: C177.1 R132.1 R275.2 U63.7 | length 327.5
  Top Layer w20: R132.1@1314.71,-1262.5 1316.68,-1264.46 ccw(c1387.39,-1193.75) 1387.39,-1293.75 1400,-1293.75 ccw(c1400,-1268.75) 1425,-1268.75 U63.7@1425,-1218.01 v8(1425,-1150)
  Bottom Layer w20: C177.1@1424.41,-1225 1424.41,-1150 v8(1425,-1150)
NetC177_2: C177.2 R274.2 R275.1 U63.6 | length 193.6
  Top Layer w20: U63.6@1475,-1218.01 v8(1475,-1150)
  Bottom Layer w20: v8(1475,-1150) 1475.59,-1150 C177.2@1475.59,-1225 R274.2@1475.59,-1275
NetC181_2: C181.2 FR6.2 R118.1 R121.1 | length 2110.9
  Top Layer w20: R118.1@762.5,562.5 R118.1@758.46,562.5 ; v2(762.5,587.5) 762.5,572.24 cw(c748.72,572.24) R118.1@758.46,562.5 ; R121.1@816.54,487.5 816.54,504.43 ccw(c758.46,504.43) R118.1@758.46,562.5
  Bottom Layer w20: v2(762.5,587.5) 832.53,587.5 cw(c832.53,406.74) 1013.29,406.74 1013.29,-1117.97 cw(c1010.59,-1117.97) FR6.2@1012.5,-1119.88 967.03,-1119.88 ccw(c967.03,-1149.41) C181.2@937.5,-1149.41
NetC184_1: C184.1 R119.2 R282.1 U57.7 | length 817
  Top Layer w20: v2(700,-50) cw(c700,50) 600,50 600,263.58 cw(c661.42,263.58) 661.42,325 U57.7@693.01,325 718.71,325 ccw(c718.71,376.29) 770,376.29 770,475.96 ccw(c758.46,475.96) 758.46,487.5 ccw(c748.72,497.24) 762.5,497.24 v2(762.5,512.5)
  Bottom Layer w10: C184.1@720,512.5 v2(762.5,512.5)
  Bottom Layer w20: v2(700,-50) 700,-25 R282.1@700.59,-25
NetC184_2: C184.2 R114.2 R118.2 R119.1 U57.6 | length 381.2
  Top Layer w20: U57.6@693.01,375 R114.2@608.46,375 ccw(c598.72,384.74) 612.5,384.74 612.5,425 cw(c675,425) 675,487.5 691.54,487.5 691.54,562.5 691.54,567.06 cw(c720.44,567.06) v2(700,587.5)
  Bottom Layer w20: v2(700,587.5) cw(c700,555.9) 722.35,578.24 C184.2@725,575.59
NetC198_2: C198.2 R284.1 U55.2 | length 205
  Top Layer w10: U55.2@593.21,-969.68 637.17,-969.68 cw(c637.17,-987.83) v3(650,-975)
  Bottom Layer w10: C198.2@512.5,-983.46 cw(c564.54,-1035.5) 564.54,-961.91 R284.1@600,-961.91 ccw(c631.6,-930.31) 631.6,-975 v3(650,-975)
NetC215_1: C215.1 R112.2 R292.1 TP7.1 U50.1 | length 370.6
  Top Layer w10: U50.1@187.5,-1468.01 v3(187.5,-1422.5) R112.2@187.5,-1388.09
  Bottom Layer w10: R292.1@112.5,-1536.91 ccw(c112.5,-1472.99) 157.7,-1518.19 C215.1@200.89,-1475 ; C215.1@198.37,-1476.04 cw(c200.89,-1478.56) C215.1@200.89,-1475 ; TP7.1@287.5,-1365 259.29,-1393.21 cw(c188.58,-1322.5) 188.58,-1422.5 v3(187.5,-1422.5) 187.5,-1452.76 ccw(c208.89,-1452.76) 193.76,-1467.88 C215.1@200.89,-1475
NetC215_2: C215.2 R111.2 R112.1 U50.2 | length 208.8
  Top Layer w10: R111.2@137.5,-1388.09 186.66,-1338.93 ccw(c184.65,-1336.91) R112.1@187.5,-1336.91
  Top Layer w20: U50.2@137.5,-1468.01 v3(137.5,-1422.5) R111.2@137.5,-1388.09
  Bottom Layer w10: C215.2@124.11,-1475 131.24,-1467.88 ccw(c116.11,-1452.76) 137.5,-1452.76 v3(137.5,-1422.5)
NetC248_2: C248.2 R110.2 R115.1 U50.3 | length 1041.8
  Top Layer w20: U50.3@87.5,-1468.01 v3(87.5,-1422.5) R110.2@87.5,-1388.09
  Int5 (ST) w20: v3(87.5,-1422.5) 87.5,-1562.5 ccw(c187.5,-1562.5) 187.5,-1662.5 667.25,-1662.5 cw(c667.25,-1747.86) v3(727.61,-1687.5)
  Bottom Layer w20: C248.2@37.5,-1524.11 37.5,-1513.92 cw(c137.5,-1513.92) 66.79,-1443.21 v3(87.5,-1422.5)
NetC272_1: C272.1 R103.1 R303.1 U44.1 | length 770
  Top Layer w10: U44.1@-446.46,-1452.76 cw(c-480.15,-1486.45) -432.5,-1486.45 -432.5,-1585 ccw(c-354.04,-1585) -409.52,-1640.48 -316.79,-1733.21 ccw(c-246.08,-1662.5) -246.08,-1762.5 R103.1@-88.09,-1762.5
  Top Layer w20: U44.1@-443.75,-1428.26 -443.75,-1350 v3(-400,-1350)
  Bottom Layer w20: C272.1@-369.34,-1368.75 -381.25,-1368.75 cw(c-381.25,-1350) v3(-400,-1350) cw(c-381.25,-1350) -381.25,-1331.25 R303.1@-369.34,-1331.25
NetC283_2: C283.2 R311.1 R312.1 R313.2 U42.4 | length 278.5
  Top Layer w5: v2(-842.52,49.21) -840.5,51.23 cw(c-795.47,6.2) U42.4@-795.47,69.88
  Bottom Layer w5: C283.2@-899.61,167.32 -914.82,156.04 -935.57,139.23 R313.2@-950.79,127.95 -950.79,99.86 R311.1@-950.79,88.58 -935.57,77.3 -914.82,60.49 R312.1@-899.61,49.21 v2(-842.52,49.21)
NetC481_1: C481.1 R165.2 U66.10 U66.11 U66.12 | length 363.1
  Top Layer w16: R165.2@1987.5,-1645.96 1992.42,-1650.89 v4(2043.75,-1650.89) ; U66.12@2079.44,-1676.48 v4(2043.75,-1676.48) v4(2043.75,-1650.89) ; U66.11@2079.44,-1650.89 v4(2043.75,-1650.89) ; U66.10@2079.44,-1625.3 v4(2043.75,-1625.3) v4(2043.75,-1650.89)
  Bottom Layer w16: C481.1@1948.87,-1650 ccw(c1949.75,-1650) 1949.75,-1650.89 v4(2043.75,-1650.89) ; v4(2043.75,-1676.48) v4(2043.75,-1650.89) ; v4(2043.75,-1625.3) v4(2043.75,-1650.89)
NetC482_2: C482.2 R168.2 R236.1 U69.10 U69.11 U69.12 | length 391.3
  Top Layer w16: R168.2@1987.5,-1045.96 1992.42,-1050.89 v4(2043.75,-1050.89) ; U69.12@2079.44,-1076.48 v4(2043.75,-1076.48) v4(2043.75,-1050.89) ; U69.11@2079.44,-1050.89 v4(2043.75,-1050.89) ; U69.10@2079.44,-1025.3 v4(2043.75,-1025.3) v4(2043.75,-1050.89)
  Bottom Layer w16: C482.2@1948.87,-975 ccw(c1974.46,-975) 1974.46,-1000.59 R236.1@2012.5,-1000.59 ccw(c2037.2,-1000.59) 2037.2,-1025.3 v4(2043.75,-1025.3) v4(2043.75,-1050.89) v4(2043.75,-1076.48)
NetC483_2: C483.2 R166.2 R233.1 U67.10 U67.11 U67.12 | length 789.6
  Top Layer w16: R166.2@1987.5,-1445.96 ccw(c1992.42,-1445.96) 1992.42,-1450.89 v4(2043.75,-1450.89) ; U67.12@2079.44,-1476.48 v4(2043.75,-1476.48) v4(2043.75,-1450.89) ; U67.11@2079.44,-1450.89 v4(2043.75,-1450.89) ; U67.10@2079.44,-1425.3 v4(2043.75,-1425.3) v4(2043.75,-1450.89)
  Bottom Layer w16: v4(2043.75,-1425.3) v4(2043.75,-1450.89) ; R233.1@2136.91,-1493.75 2061.02,-1493.75 cw(c2061.02,-1476.48) v4(2043.75,-1476.48) v4(2043.75,-1450.89) ; C483.2@2338.63,-1368.75 ccw(c2288.56,-1368.75) 2288.56,-1318.67 2131.33,-1318.67 ccw(c2131.33,-1375) 2075,-1375 2075,-1419.64 cw(c2043.75,-1419.64) v4(2043.75,-1450.89)
NetC484_1: C484.1 R167.2 U68.10 U68.11 U68.12 | length 604.6
  Top Layer w16: R167.2@1987.5,-1245.96 1992.42,-1250.89 v4(2043.75,-1250.89) ; U68.12@2079.44,-1276.48 v4(2043.75,-1276.48) v4(2043.75,-1250.89) ; U68.11@2079.44,-1250.89 v4(2043.75,-1250.89) ; U68.10@2079.44,-1225.3 v4(2043.75,-1225.3) v4(2043.75,-1250.89)
  Bottom Layer w16: v4(2043.75,-1225.3) v4(2043.75,-1250.89) v4(2043.75,-1276.48) ccw(c2054.77,-1276.48) 2054.77,-1287.5 2276.13,-1287.5 ccw(c2276.13,-1225) C484.1@2338.63,-1225
NetD1_2: D1.2 R4.2 R6.2 | length 117.9
  Top Layer w10: D1.2@-3048.47,400 R4.2@-2988.09,400 -2979.34,391.25 cw(c-3020,350.59) R6.2@-2962.5,350.59
NetD3_2: D3.2 R199.4 | length 12772
  Top Layer w50: 2387.5,1507.81 2387.5,1400 ccw(c2487.5,1400) 2487.5,1300 v12(2987.5,1300)
  Top Layer w60: v12(1025,-1637.5) 1025,-1563.58 D3.2@1038.58,-1550
  Int5 (ST) w100: v12(1025,-1637.5) 1025,-1775 ccw(c1125,-1775) 1125,-1875 3237.5,-1875 ccw(c3237.5,-1775) 3337.5,-1775 3337.5,1225 ccw(c3262.5,1225) 3262.5,1300 v12(2987.5,1300)
  Int6 (SB) w100: v12(1025,-1637.5) 1025,-1775 ccw(c1125,-1775) 1125,-1875 3237.5,-1875 ccw(c3237.5,-1775) 3337.5,-1775 3337.5,1225 ccw(c3262.5,1225) 3262.5,1300 v12(2987.5,1300)
NetDS1_1: DS1.1 Q1.3 | length 94.5
  Top Layer w16: Q1.3@49.21,782.48 DS1.1@49.21,876.97
NetDS1_2: DS1.2 R109.2 | length 83.7
  Top Layer w15.98: DS1.2@49.21,953.74 R109.2@49.21,1037.4
NetDS2_1: DS2.1 Q6.3 | length 67.3
  Bottom Layer w10: Q6.3@650,1644.29 DS2.1@650,1711.61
